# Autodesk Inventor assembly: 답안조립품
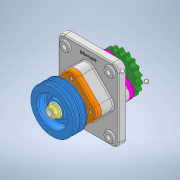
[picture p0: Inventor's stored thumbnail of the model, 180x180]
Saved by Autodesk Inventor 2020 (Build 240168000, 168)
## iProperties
Created: 2021-07
Part Number: 답안조립품
Document SubType Name: Assembly
Designer: Owner
Author: Owner
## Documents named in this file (16)
- C:\Users\Owner\Desktop\710707V1019\답안조립품.iam
- C:\Users\Owner\Desktop\710707V1019\본체.ipt
- C:\Users\Owner\Desktop\710707V1019\M16 너트.ipt
- C:\Users\Owner\Desktop\710707V1019\V-벨트풀리.ipt
- C:\Users\Owner\Desktop\710707V1019\멈춤나사 M4.ipt
- C:\Users\Owner\Desktop\710707V1019\베어링 6206.ipt
- C:\Users\Owner\Desktop\710707V1019\볼트 M6.ipt
- C:\Users\Owner\Desktop\710707V1019\부시.ipt
- C:\Users\Owner\Desktop\710707V1019\오일실 30x42x8.ipt
- C:\Users\Owner\Desktop\710707V1019\오일실 30x45x8.ipt
- C:\Users\Owner\Desktop\710707V1019\체인 스프로킷.ipt
- C:\Users\Owner\Desktop\710707V1019\축.ipt
- C:\Users\Owner\Desktop\710707V1019\커버A.ipt
- C:\Users\Owner\Desktop\710707V1019\커버B.ipt
- C:\Users\Owner\Desktop\710707V1019\키 6x6x18.ipt
- C:\Users\Owner\Desktop\710707V1019\키 6x6x20.ipt
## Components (3 placed, 2 different names)
1. M16 너트:1
2. V-벨트풀리:1 — 각도:2
3. M16 너트:2
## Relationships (1: Angle 1)
- 각도:2 [Angle]: V-벨트풀리:1
